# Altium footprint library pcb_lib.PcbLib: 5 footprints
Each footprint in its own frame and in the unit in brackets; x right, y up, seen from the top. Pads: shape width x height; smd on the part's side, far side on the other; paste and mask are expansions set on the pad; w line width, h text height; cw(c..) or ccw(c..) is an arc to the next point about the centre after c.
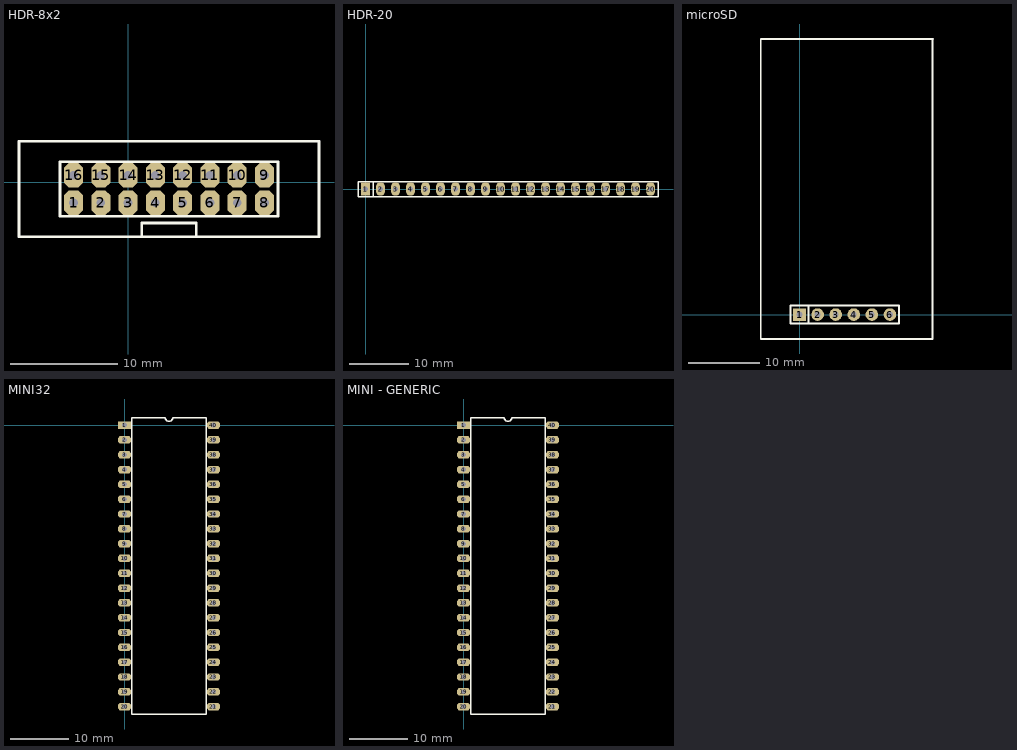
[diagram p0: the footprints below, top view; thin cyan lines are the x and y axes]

## HDR-8x2 [mil]
pads (16):
  oct 70x90 hole 32: 1(-200,-75) 2(-100,-75) 3(0,-75) 4(100,-75) 5(200,-75) 6(300,-75) 7(400,-75) 8(500,-75) 9(500,25) 10(400,25) 11(300,25) 12(200,25) 13(100,25) 14(0,25) 15(-100,25) 16(-200,25)
Top Overlay:
  lines w10: 50,-200 50,-150 ; 50,-190 50,-150 ; 250,-200 250,-150 50,-150 ; 700,149.33 700,-200 -400,-200 -400,150 700,150 ; -250,-125 -250,-25 -250,75 550,75 550,-25 550,-125 -250,-125
3D body: height 350.39, standoff -137.8, extent -398.43,-202.16 700,152.16

## HDR-20 [mil]
pads (20):
  rect 60x90 hole 32: 1(0,0)
  oval 60x90 hole 32: 2(100,0) 3(200,0) 4(300,0) 5(400,0) 6(500,0) 7(600,0) 8(700,0) 9(800,0) 10(900,0) 11(1000,0) 12(1100,0) 13(1200,0) 14(1300,0) 15(1400,0) 16(1500,0) 17(1600,0) 18(1700,0) 19(1800,0) 20(1900,0)
Top Overlay:
  lines w10: 50,-50 50,50 ; -50,-50 1950,-50 1950,50 -50,50 -50,-50
3D body: height 414.96, standoff -118.11, extent -50.2,-49.21 1950,49.21

## microSD [mil]
pads (6):
  rect 70x70 hole 32: 1(0,0)
  round 70 hole 32: 2(100,0) 3(200,0) 4(300,0) 5(400,0) 6(500,0)
Top Overlay:
  lines w10: 50,-50 50,50 ; -215,-135 -215,1525 740,1525 735,1520 735,-135 -215,-135 ; -50,-50 550,-50 550,50 -50,50 -50,-50
3D body: height 635.98, standoff 372.2, extent -217.44,-325 727.44,1521.46

## MINI32 [mil]
pads (40):
  rect 90x50 hole 32: 1(0,0)
  oct 90x50 hole 32: 2(0,-100) 3(0,-200) 4(0,-300) 5(0,-400) 6(0,-500) 7(0,-600) 8(0,-700) 9(0,-800) 10(0,-900) 11(0,-1000) 12(0,-1100) 13(0,-1200) 14(0,-1300) 15(0,-1400) 16(0,-1500) 17(0,-1600) 18(0,-1700) 19(0,-1800) 20(0,-1900) 21(600,-1900) 22(600,-1800) 23(600,-1700) 24(600,-1600) 25(600,-1500) 26(600,-1400) 27(600,-1300) 28(600,-1200) 29(600,-1100) 30(600,-1000) 31(600,-900) 32(600,-800) 33(600,-700) 34(600,-600) 35(600,-500) 36(600,-400) 37(600,-300) 38(600,-200) 39(600,-100) 40(600,0)
Top Overlay:
  lines w10: 50,-1950 50,50 275,50 ccw(c300,50) 325,50 550,50 550,-1950 50,-1950
3D body: height 337.48, standoff -40.94, extent -50,-1945 650,55

## MINI - GENERIC [mil]
pads (40):
  rect 90x50 hole 32: 1(0,0)
  oct 90x50 hole 32: 2(0,-100) 3(0,-200) 4(0,-300) 5(0,-400) 6(0,-500) 7(0,-600) 8(0,-700) 9(0,-800) 10(0,-900) 11(0,-1000) 12(0,-1100) 13(0,-1200) 14(0,-1300) 15(0,-1400) 16(0,-1500) 17(0,-1600) 18(0,-1700) 19(0,-1800) 20(0,-1900) 21(600,-1900) 22(600,-1800) 23(600,-1700) 24(600,-1600) 25(600,-1500) 26(600,-1400) 27(600,-1300) 28(600,-1200) 29(600,-1100) 30(600,-1000) 31(600,-900) 32(600,-800) 33(600,-700) 34(600,-600) 35(600,-500) 36(600,-400) 37(600,-300) 38(600,-200) 39(600,-100) 40(600,0)
Top Overlay:
  lines w10: 50,-1950 550,-1950 550,50 325,50 cw(c300,50) 275,50 50,50 50,-1950
3D body: height 567.48, standoff 189.06, extent -50,-1945 650,55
